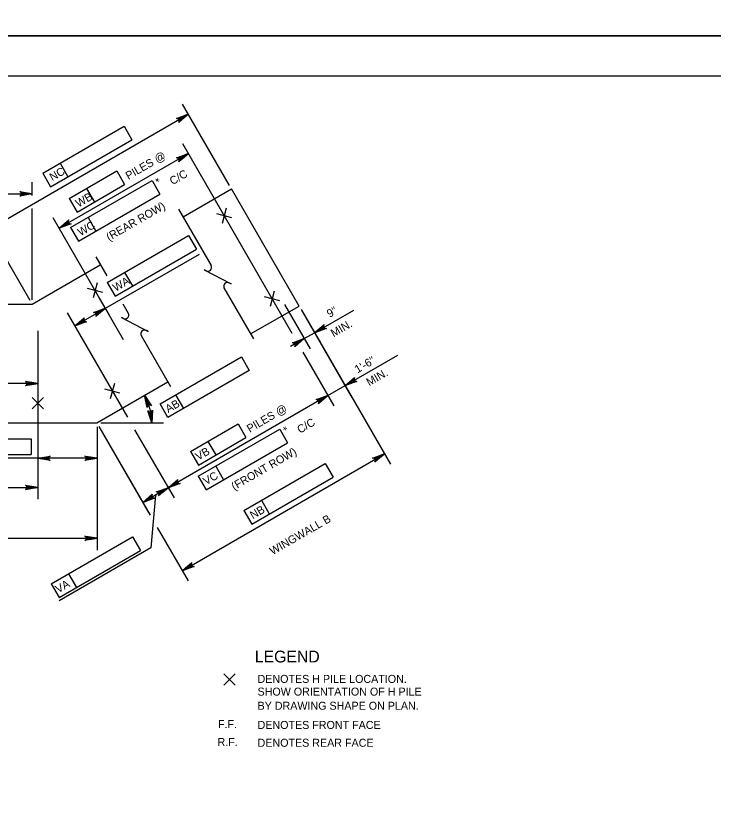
# Model space of a CAD drawing. Extents: x 638340 to 640242, y 295465 to 298435.
# Drawn here: x 639639.2 to 639900.6, y 296364 to 296661 of the extents above; entities that cross this region are included whole.
import ezdxf

# ---------------------------------------------------------------- set-up
doc = ezdxf.new("R2010")
doc.units = 0
for name, color, linetype in [('2', 7, 'Continuous'), ('4', 7, 'Continuous'), ('Level 2', 7, 'Continuous'), ('Level 3', 7, 'Continuous'), ('Level 4', 7, 'Continuous'), ('PLT-BNDY', 7, 'Continuous')]:
    doc.layers.add(name, color=color, linetype=linetype)

# ---------------------------------------------------------------- blocks, each defined once
blk = doc.blocks.new('PILE')
at = {"layer": '2'}
for p, q in [((-2.651625, -2.651625), (2.651625, 2.651625)), ((-2.651625, 2.651625), (2.651625, -2.651625))]:
    blk.add_line(p, q, dxfattribs=at)

msp = doc.modelspace()

# ---------------------------------------------------------------- linework, layer by layer
at = {"layer": '2'}
msp.add_line((639316.46, 296638.46), (640102.69, 296638.46), dxfattribs=at)
at = {"layer": 'Level 2'}
for p, q in [((639719.28, 296597.39), (639701.66, 296627.91)), ((639629.17, 296580.95), (639703.87, 296624.08)), ((639649.29, 296601.95), (639679.8, 296619.56)), ((639679.8, 296619.56), (639682.75, 296614.46)), ((639652.24, 296596.84), (639682.75, 296614.46)), ((639701.68, 296613.14), (639742.73, 296542.03)), ((639703.89, 296609.31), (639655.48, 296581.36)), ((639655.82, 296605.72), (639658.77, 296600.62)), ((639659.22, 296592.5), (639677.06, 296602.8)), ((639677.06, 296602.8), (639680.01, 296597.69)), ((639649.29, 296601.95), (639652.24, 296596.84)), ((639659.77, 296581.6), (639690.29, 296599.21)), ((639690.29, 296599.21), (639693.24, 296594.1)), ((639645.35, 296593.55), (639645.35, 296598.67)), ((639662.17, 296587.39), (639680.01, 296597.69)), ((639665.76, 296596.27), (639668.7, 296591.16)), ((639534.56, 296594.25), (639645.35, 296594.25)), ((639662.72, 296576.5), (639693.24, 296594.1)), ((639659.22, 296592.5), (639662.17, 296587.39)), ((639645.35, 296554.46), (639645.35, 296588.7)), ((639644.58, 296554.26), (639626.96, 296584.78)), ((639679.61, 296539.56), (639653.27, 296585.19)), ((639666.31, 296585.38), (639669.26, 296580.27)), ((639659.77, 296581.6), (639662.72, 296576.5)), ((639673.48, 296561.03), (639704, 296578.63)), ((639704, 296578.63), (639706.94, 296573.53)), ((639676.42, 296555.92), (639706.94, 296573.53)), ((639672.81, 296551.35), (639708.02, 296571.67)), ((639680.01, 296564.8), (639682.96, 296559.7)), ((639673.48, 296561.03), (639676.42, 296555.92)), ((639674.31, 296548.76), (639670.6, 296555.18)), ((639739.92, 296552.79), (639749.54, 296536.14)), ((639658.44, 296549.67), (639681.07, 296510.47)), ((639661.3, 296544.7), (639672.81, 296551.35)), ((639746.14, 296550.86), (639753.37, 296538.35)), ((639746.14, 296550.86), (639764.82, 296518.51)), ((639746.14, 296550.86), (639779.6, 296492.92)), ((639751.16, 296542.18), (639765.91, 296550.69)), ((639647.45, 296542.88), (639647.45, 296479.79)), ((639747.33, 296539.96), (639742.22, 296537.02)), ((639747.33, 296539.96), (639751.16, 296542.18)), ((639746.83, 296534.94), (639758.44, 296514.83)), ((639762.61, 296522.34), (639782.4, 296533.77)), ((639693.29, 296515.46), (639723.79, 296533.1)), ((639723.79, 296533.1), (639726.74, 296528)), ((639726.74, 296528), (639696.24, 296510.35)), ((639647.45, 296523.11), (639622.89, 296523.11)), ((639756.23, 296518.66), (639762.61, 296522.34)), ((639702.16, 296513.78), (639699.21, 296518.88)), ((639756.23, 296518.66), (639696.31, 296484.07)), ((639753.68, 296517.18), (639751.12, 296515.71)), ((639696.24, 296510.35), (639693.29, 296515.46)), ((639670.32, 296507.08), (639689, 296474.74)), ((639670.32, 296507.08), (639689.54, 296473.79)), ((639671.09, 296508.41), (639694.62, 296508.41)), ((639704.69, 296497.66), (639722.52, 296507.99)), ((639722.52, 296507.99), (639725.47, 296502.9)), ((639669.75, 296506.88), (639669.75, 296460.68)), ((639683.76, 296505.82), (639698.52, 296480.24)), ((639707.63, 296488.39), (639738.12, 296506.05)), ((639738.12, 296506.05), (639741.07, 296500.95)), ((639609.79, 296502.38), (639645.02, 296502.38)), ((639645.02, 296502.38), (639645.02, 296496.49)), ((639707.65, 296492.56), (639725.47, 296502.9)), ((639711.22, 296501.45), (639714.18, 296496.35)), ((639710.58, 296483.29), (639741.07, 296500.95)), ((639609.79, 296496.49), (639645.02, 296496.49)), ((639701.57, 296452.97), (639777.39, 296496.75)), ((639704.69, 296497.66), (639707.65, 296492.56)), ((639669.75, 296495.09), (639606.61, 296495.09)), ((639714.16, 296492.18), (639717.11, 296487.08)), ((639724.72, 296475.57), (639755.23, 296493.19)), ((639755.23, 296493.19), (639758.18, 296488.08)), ((639707.63, 296488.39), (639710.58, 296483.29)), ((639727.67, 296470.47), (639758.18, 296488.08)), ((639532.46, 296484.21), (639647.45, 296484.21)), ((639696.31, 296484.07), (639686.79, 296478.57)), ((639691.6, 296481.34), (639689.78, 296461.52)), ((639731.26, 296479.35), (639734.2, 296474.24)), ((639724.72, 296475.57), (639727.67, 296470.47)), ((639692.24, 296469.13), (639703.78, 296449.14)), ((639652.46, 296448.05), (639682.98, 296465.65)), ((639682.98, 296465.65), (639685.93, 296460.55)), ((639510.35, 296465.1), (639669.75, 296465.1)), ((639655.41, 296442.94), (639685.93, 296460.55)), ((639689.78, 296461.52), (639655.49, 296441.72)), ((639658.99, 296451.82), (639661.94, 296446.72)), ((639652.46, 296448.05), (639655.41, 296442.94))]:
    msp.add_line(p, q, dxfattribs=at)
for points in [[(639703.87, 296624.08), (639700.28, 296621), (639700.46, 296621.39), (639700.47, 296621.76), (639700.36, 296622.05), (639700.16, 296622.3), (639699.84, 296622.48), (639699.41, 296622.51), (639703.87, 296624.08), (639699.84, 296622.48), (639700.16, 296622.3), (639703.87, 296624.08), (639700.36, 296622.05), (639700.47, 296621.76), (639703.87, 296624.08), (639700.46, 296621.39)], [(639703.89, 296609.31), (639700.3, 296606.23), (639700.48, 296606.63), (639700.49, 296606.99), (639700.38, 296607.29), (639700.18, 296607.53), (639699.86, 296607.71), (639699.42, 296607.74), (639703.89, 296609.31), (639699.86, 296607.71), (639700.18, 296607.53), (639703.89, 296609.31), (639700.38, 296607.29), (639700.49, 296606.99), (639703.89, 296609.31), (639700.48, 296606.63)], [(639645.35, 296594.25), (639640.7, 296593.38), (639641.06, 296593.62), (639641.24, 296593.94), (639641.29, 296594.25), (639641.24, 296594.56), (639641.06, 296594.87), (639640.7, 296595.12), (639645.35, 296594.25), (639641.06, 296594.87), (639641.24, 296594.56), (639645.35, 296594.25), (639641.29, 296594.25), (639641.24, 296593.94), (639645.35, 296594.25), (639641.06, 296593.62)], [(639655.48, 296581.36), (639659.07, 296584.45), (639658.89, 296584.05), (639658.88, 296583.69), (639658.99, 296583.39), (639659.19, 296583.15), (639659.51, 296582.97), (639659.94, 296582.93), (639655.48, 296581.36), (639659.51, 296582.97), (639659.19, 296583.15), (639655.48, 296581.36), (639658.99, 296583.39), (639658.88, 296583.69), (639655.48, 296581.36), (639658.89, 296584.05)], [(639672.81, 296551.35), (639669.22, 296548.27), (639669.4, 296548.66), (639669.41, 296549.02), (639669.3, 296549.32), (639669.1, 296549.56), (639668.78, 296549.74), (639668.34, 296549.78), (639672.81, 296551.35), (639668.78, 296549.74), (639669.1, 296549.56), (639672.81, 296551.35), (639669.3, 296549.32), (639669.41, 296549.02), (639672.81, 296551.35), (639669.4, 296548.66)], [(639661.3, 296544.7), (639664.9, 296547.79), (639664.71, 296547.39), (639664.71, 296547.03), (639664.82, 296546.73), (639665.02, 296546.49), (639665.33, 296546.31), (639665.77, 296546.27), (639661.3, 296544.7), (639665.33, 296546.31), (639665.02, 296546.49), (639661.3, 296544.7), (639664.82, 296546.73), (639664.71, 296547.03), (639661.3, 296544.7), (639664.71, 296547.39)], [(639751.16, 296542.18), (639754.75, 296545.26), (639754.56, 296544.86), (639754.56, 296544.5), (639754.67, 296544.2), (639754.87, 296543.96), (639755.19, 296543.78), (639755.62, 296543.75), (639751.16, 296542.18), (639755.19, 296543.78), (639754.87, 296543.96), (639751.16, 296542.18), (639754.67, 296544.2), (639754.56, 296544.5), (639751.16, 296542.18), (639754.56, 296544.86)], [(639747.33, 296539.96), (639743.74, 296536.88), (639743.92, 296537.28), (639743.93, 296537.64), (639743.82, 296537.94), (639743.62, 296538.18), (639743.3, 296538.36), (639742.87, 296538.39), (639747.33, 296539.96), (639743.3, 296538.36), (639743.62, 296538.18), (639747.33, 296539.96), (639743.82, 296537.94), (639743.93, 296537.64), (639747.33, 296539.96), (639743.92, 296537.28)], [(639762.61, 296522.34), (639766.2, 296525.42), (639766.02, 296525.03), (639766.01, 296524.66), (639766.12, 296524.37), (639766.32, 296524.12), (639766.64, 296523.95), (639767.08, 296523.91), (639762.61, 296522.34), (639766.64, 296523.95), (639766.32, 296524.12), (639762.61, 296522.34), (639766.12, 296524.37), (639766.01, 296524.66), (639762.61, 296522.34), (639766.02, 296525.03)], [(639647.45, 296523.11), (639642.8, 296522.24), (639643.16, 296522.49), (639643.34, 296522.8), (639643.4, 296523.11), (639643.34, 296523.42), (639643.16, 296523.73), (639642.8, 296523.98), (639647.45, 296523.11), (639643.16, 296523.73), (639643.34, 296523.42), (639647.45, 296523.11), (639643.4, 296523.11), (639643.34, 296522.8), (639647.45, 296523.11), (639643.16, 296522.49)], [(639687.44, 296518.71), (639690.11, 296514.81), (639689.74, 296515.04), (639689.38, 296515.08), (639689.07, 296515), (639688.81, 296514.83), (639688.6, 296514.53), (639688.51, 296514.1), (639687.44, 296518.71), (639688.6, 296514.53), (639688.81, 296514.83), (639687.44, 296518.71), (639689.07, 296515), (639689.38, 296515.08), (639687.44, 296518.71), (639689.74, 296515.04)], [(639756.23, 296518.66), (639752.64, 296515.57), (639752.82, 296515.97), (639752.83, 296516.33), (639752.72, 296516.63), (639752.52, 296516.87), (639752.2, 296517.05), (639751.76, 296517.09), (639756.23, 296518.66), (639752.2, 296517.05), (639752.52, 296516.87), (639756.23, 296518.66), (639752.72, 296516.63), (639752.83, 296516.33), (639756.23, 296518.66), (639752.82, 296515.97)], [(639690.19, 296508.42), (639688.66, 296512.9), (639688.96, 296512.58), (639689.29, 296512.44), (639689.61, 296512.44), (639689.91, 296512.53), (639690.19, 296512.76), (639690.39, 296513.15), (639690.19, 296508.42), (639690.19, 296512.76), (639689.91, 296512.53), (639690.19, 296508.42), (639689.61, 296512.44), (639689.29, 296512.44), (639690.19, 296508.42), (639688.96, 296512.58)], [(639647.45, 296495.09), (639652.1, 296495.96), (639651.75, 296495.72), (639651.56, 296495.4), (639651.51, 296495.09), (639651.56, 296494.78), (639651.75, 296494.47), (639652.1, 296494.22), (639647.45, 296495.09), (639651.75, 296494.47), (639651.56, 296494.78), (639647.45, 296495.09), (639651.51, 296495.09), (639651.56, 296495.4), (639647.45, 296495.09), (639651.75, 296495.72)], [(639669.75, 296495.09), (639665.1, 296494.22), (639665.46, 296494.47), (639665.64, 296494.78), (639665.7, 296495.09), (639665.64, 296495.4), (639665.46, 296495.72), (639665.1, 296495.96), (639669.75, 296495.09), (639665.46, 296495.72), (639665.64, 296495.4), (639669.75, 296495.09), (639665.7, 296495.09), (639665.64, 296494.78), (639669.75, 296495.09), (639665.46, 296494.47)], [(639777.39, 296496.75), (639773.79, 296493.66), (639773.98, 296494.06), (639773.98, 296494.42), (639773.87, 296494.72), (639773.67, 296494.96), (639773.36, 296495.14), (639772.92, 296495.18), (639777.39, 296496.75), (639773.36, 296495.14), (639773.67, 296494.96), (639777.39, 296496.75), (639773.87, 296494.72), (639773.98, 296494.42), (639777.39, 296496.75), (639773.98, 296494.06)], [(639696.31, 296484.07), (639699.91, 296487.15), (639699.72, 296486.75), (639699.72, 296486.39), (639699.83, 296486.09), (639700.03, 296485.85), (639700.34, 296485.67), (639700.78, 296485.64), (639696.31, 296484.07), (639700.34, 296485.67), (639700.03, 296485.85), (639696.31, 296484.07), (639699.83, 296486.09), (639699.72, 296486.39), (639696.31, 296484.07), (639699.72, 296486.75)], [(639647.45, 296484.21), (639642.8, 296483.34), (639643.16, 296483.59), (639643.34, 296483.9), (639643.4, 296484.21), (639643.34, 296484.52), (639643.16, 296484.84), (639642.8, 296485.08), (639647.45, 296484.21), (639643.16, 296484.84), (639643.34, 296484.52), (639647.45, 296484.21), (639643.4, 296484.21), (639643.34, 296483.9), (639647.45, 296484.21), (639643.16, 296483.59)], [(639696.31, 296484.07), (639692.72, 296480.98), (639692.91, 296481.38), (639692.91, 296481.74), (639692.8, 296482.04), (639692.6, 296482.28), (639692.28, 296482.46), (639691.85, 296482.5), (639696.31, 296484.07), (639692.28, 296482.46), (639692.6, 296482.28), (639696.31, 296484.07), (639692.8, 296482.04), (639692.91, 296481.74), (639696.31, 296484.07), (639692.91, 296481.38)], [(639686.79, 296478.57), (639690.38, 296481.65), (639690.19, 296481.25), (639690.19, 296480.89), (639690.3, 296480.59), (639690.5, 296480.35), (639690.82, 296480.17), (639691.25, 296480.14), (639686.79, 296478.57), (639690.82, 296480.17), (639690.5, 296480.35), (639686.79, 296478.57), (639690.3, 296480.59), (639690.19, 296480.89), (639686.79, 296478.57), (639690.19, 296481.25)], [(639669.75, 296465.1), (639665.1, 296464.23), (639665.46, 296464.48), (639665.64, 296464.79), (639665.7, 296465.1), (639665.64, 296465.41), (639665.46, 296465.73), (639665.1, 296465.97), (639669.75, 296465.1), (639665.46, 296465.73), (639665.64, 296465.41), (639669.75, 296465.1), (639665.7, 296465.1), (639665.64, 296464.79), (639669.75, 296465.1), (639665.46, 296464.48)], [(639701.57, 296452.97), (639705.16, 296456.05), (639704.97, 296455.65), (639704.97, 296455.29), (639705.08, 296455), (639705.28, 296454.75), (639705.6, 296454.58), (639706.03, 296454.54), (639701.57, 296452.97), (639705.6, 296454.58), (639705.28, 296454.75), (639701.57, 296452.97), (639705.08, 296455), (639704.97, 296455.29), (639701.57, 296452.97), (639704.97, 296455.65)]]:
    msp.add_lwpolyline(points, dxfattribs=at)
for points in [[(639701.07, 296623.03), (639701.56, 296622.18), (639703.87, 296624.08)], [(639701.09, 296608.26), (639701.58, 296607.41), (639703.89, 296609.31)], [(639657.79, 296583.26), (639658.28, 296582.41), (639655.48, 296581.36)], [(639670.01, 296550.3), (639670.5, 296549.45), (639672.81, 296551.35)], [(639663.61, 296546.6), (639664.1, 296545.75), (639661.3, 296544.7)], [(639753.47, 296544.08), (639753.96, 296543.22), (639751.16, 296542.18)], [(639744.53, 296538.92), (639745.02, 296538.07), (639747.33, 296539.96)], [(639644.5, 296523.6), (639644.5, 296522.62), (639647.45, 296523.11)], [(639764.92, 296524.24), (639765.41, 296523.39), (639762.61, 296522.34)], [(639753.43, 296517.61), (639753.92, 296516.76), (639756.23, 296518.66)], [(639753.43, 296517.61), (639753.92, 296516.76), (639756.23, 296518.66)], [(639650.4, 296495.58), (639650.4, 296494.6), (639647.45, 296495.09)], [(639666.61, 296495.58), (639666.61, 296494.6), (639669.56, 296495.09)], [(639774.59, 296495.7), (639775.08, 296494.84), (639777.39, 296496.75)], [(639644.5, 296484.7), (639644.5, 296483.72), (639647.45, 296484.21)], [(639693.52, 296483.02), (639694.01, 296482.16), (639696.31, 296484.07)], [(639698.62, 296485.96), (639699.11, 296485.11), (639696.31, 296484.07)], [(639689.1, 296480.46), (639689.59, 296479.61), (639686.79, 296478.57)], [(639666.8, 296465.59), (639666.8, 296464.61), (639669.75, 296465.1)], [(639703.87, 296454.87), (639704.37, 296454.02), (639701.57, 296452.97)]]:
    msp.add_lwpolyline(points, close=True, dxfattribs=at)
msp.add_arc((639669.56, 296508.41), 20.64, 359.9703, 29.9903, dxfattribs=at)
at = {"layer": 'Level 3'}
for p, q in [((639701.89, 296585.57), (639720.05, 296596.06)), ((639745.38, 296552.19), (639720.05, 296596.06)), ((639645.35, 296552.93), (639670.87, 296567.66)), ((639603.57, 296552.93), (639645.35, 296552.93)), ((639727.22, 296541.7), (639745.38, 296552.19)), ((639669.56, 296508.41), (639696.2, 296523.8)), ((639603.57, 296508.41), (639669.56, 296508.41))]:
    msp.add_line(p, q, dxfattribs=at)
at = {"layer": 'Level 4'}
for p, q in [((639700.24, 296588.43), (639712.4, 296567.36)), ((639669.2, 296570.57), (639673.31, 296563.44)), ((639717.25, 296558.96), (639728.29, 296539.85)), ((639679.31, 296553.05), (639681.36, 296549.5)), ((639686.21, 296541.1), (639697.24, 296521.99))]:
    msp.add_line(p, q, dxfattribs=at)
for points in [[(639710.47, 296565.42), (639709.84, 296565.76), (639719.88, 296560.45), (639719.2, 296560.81)], [(639679.42, 296547.56), (639678.8, 296547.89), (639688.83, 296542.59), (639688.16, 296542.95)]]:
    msp.add_lwpolyline(points, dxfattribs=at)
for centre, start, end in [((639711.18, 296566.65), 240, 30), ((639718.54, 296559.56), 62.1328, 204.6714), ((639680.13, 296548.79), 240, 30), ((639687.49, 296541.69), 62.1328, 204.6714)]:
    msp.add_arc(centre, 1.42, start, end, dxfattribs=at)
at = {"layer": 'PLT-BNDY'}
for points in [[(639276.46, 297247.46), (640117.46, 297247.46), (640117.46, 296653.46), (639276.46, 296653.46)], [(639276.46, 296653.46), (640117.46, 296653.46), (640117.46, 296059.46), (639276.46, 296059.46)]]:
    msp.add_lwpolyline(points, close=True, dxfattribs=at)

# ---------------------------------------------------------------- block references
at = {"layer": 'Level 2', "xscale": 0.7859001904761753, "yscale": -0.7859001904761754, "rotation": -149.99999999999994}
for p in [(639717.36, 296585.99), (639668.95, 296558.04), (639735.31, 296554.89), (639675.4, 296520.29)]:
    msp.add_blockref('PILE', p, dxfattribs=at)
at = {"layer": 'Level 2', "xscale": 0.7859001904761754, "yscale": 0.7859001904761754}
for p in [(639647.46, 296515.78), (639719.33, 296412.17)]:
    msp.add_blockref('PILE', p, dxfattribs=at)

# ---------------------------------------------------------------- texts
at = {"layer": '4'}
msp.add_text('LEGEND', height=4.429, dxfattribs=at).set_placement((639728.78, 296418.57))
at = {"layer": 'Level 2'}
for s, height, rotation, p in [('PILES @', 3, 30, (639681.42, 296599.43)), ('NC', 3, 29.9382, (639652.9, 296598.93)), ('C/C', 3, 29.9382, (639697.92, 296597.43)), ('*', 3, 59.9382, (639693.8, 296597.63)), ('WB', 3, 29.9382, (639662.7, 296589.1)), ('(REAR ROW)', 3, 30, (639674.16, 296576.47)), ('WC', 3, 29.9382, (639663.45, 296578.3)), ('WA', 3, 29.9382, (639676.63, 296557.5)), ('9"', 3, 30, (639756.85, 296547.72)), ('MIN.', 3, 30, (639758.32, 296540.42)), ('1\'-6"', 3, 30, (639767.29, 296526.91)), ('MIN.', 3, 30, (639771.67, 296522.08)), ('AB', 3, 30.0491, (639696.34, 296512.06)), ('PILES @', 3, 30.0982, (639726.88, 296504.64)), ('*', 3, 60.0364, (639741.62, 296504.47)), ('C/C', 3, 30.0364, (639745.74, 296504.29)), ('VB', 3, 30.0364, (639707.59, 296494.21)), ('(FRONT ROW)', 3.0001, 30.0982, (639721.09, 296483)), ('VC', 3, 30.0364, (639710.53, 296484.94)), ('NB', 3, 29.9382, (639728.04, 296472.23)), ('WINGWALL B', 3, 30, (639735.46, 296458.75)), ('VA', 3, 29.9382, (639655.13, 296444.46))]:
    msp.add_text(s, height=height, rotation=rotation, dxfattribs=at).set_placement(p)
for s, p in [('DENOTES H PILE LOCATION.', (639729.82, 296410.91)), ('SHOW ORIENTATION OF H PILE', (639729.82, 296406.14)), ('BY DRAWING SHAPE ON PLAN.', (639729.82, 296400.85))]:
    msp.add_text(s, height=3.0001, dxfattribs=at).set_placement(p)
at = {"layer": 'Level 4'}
for s, height, p in [('F.F.', 3, (639714.99, 296393.95)), ('DENOTES FRONT FACE', 3.0001, (639729.83, 296393.65)), ('R.F.', 3, (639714.82, 296387.26)), ('DENOTES REAR FACE', 3.0001, (639729.83, 296386.97))]:
    msp.add_text(s, height=height, dxfattribs=at).set_placement(p)

doc.saveas('drawing.dxf')
